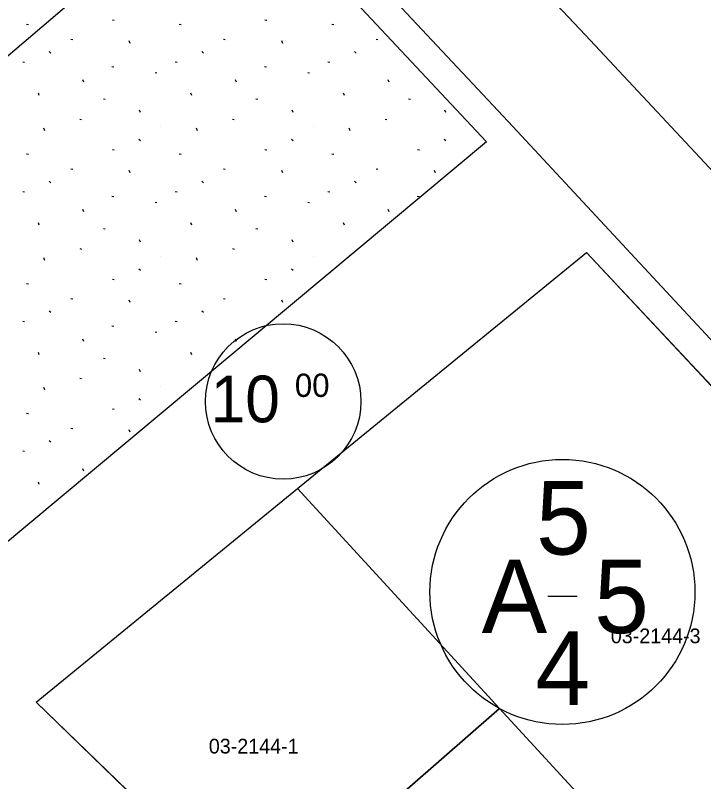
# Model space of a CAD drawing. Extents: x 413946 to 415528, y 4453939 to 4454944.
# Drawn here: x 413992.5 to 414039.2, y 4454203.5 to 4454255.6 of the extents above; entities that cross this region are included whole.
import ezdxf

# ---------------------------------------------------------------- set-up
doc = ezdxf.new("R2010")
doc.units = 0
for name, color, linetype in [('0_KADASTRO', 7, 'Continuous'), ('Level 28', 7, 'Continuous'), ('Level 41', 7, 'Continuous'), ('Level 54', 7, 'Continuous'), ('Level 62', 7, 'Continuous'), ('SEMBOL', 7, 'Continuous')]:
    doc.layers.add(name, color=color, linetype=linetype)

msp = doc.modelspace()

# ---------------------------------------------------------------- linework, layer by layer
at = {"layer": '0_KADASTRO'}
msp.add_lwpolyline([(413945.566, 4454269.246), (413976.93, 4454296.8), (414006.54, 4454265.23), (413971.15, 4454235.05), (413945.566, 4454264.88)], dxfattribs=at)
for points in [[(414011.66, 4454223.42), (414031.3, 4454239.46), (414063.26, 4454205.27), (414044.87, 4454187.28), (414025.39, 4454208.48)], [(413993.9, 4454208.91), (414011.66, 4454223.42), (414025.39, 4454208.48), (414009.07, 4454194.23)], [(414009.07, 4454194.23), (414025.39, 4454208.48), (414044.87, 4454187.28), (414030.63, 4454173.35)]]:
    msp.add_lwpolyline(points, close=True, dxfattribs=at)
at = {"layer": 'Level 28'}
for p, q in [((413962.499, 4454313.068), (414024.505, 4454246.98)), ((414024.505, 4454246.98), (413987.639, 4454216.206)), ((414011.66, 4454223.42), (414031.3, 4454239.46)), ((414031.3, 4454239.46), (414063.26, 4454205.27)), ((413993.9, 4454208.91), (414011.66, 4454223.42)), ((414009.07, 4454194.23), (413993.9, 4454208.91))]:
    msp.add_line(p, q, dxfattribs=at)
at = {"layer": 'Level 41'}
for p, q in [((413999.081, 4454255.258), (413999.208, 4454255.233)), ((413999.081, 4454255.258), (413999.208, 4454255.233)), ((414009.449, 4454255.258), (414009.576, 4454255.233)), ((414009.449, 4454255.258), (414009.576, 4454255.233)), ((413993.261, 4454254.964), (413993.388, 4454254.94)), ((413993.261, 4454254.964), (413993.388, 4454254.94)), ((414003.629, 4454254.964), (414003.756, 4454254.94)), ((414003.629, 4454254.964), (414003.756, 4454254.94)), ((414013.997, 4454254.964), (414014.124, 4454254.94)), ((414013.997, 4454254.964), (414014.124, 4454254.94)), ((413996.261, 4454253.939), (413996.386, 4454253.915)), ((413996.261, 4454253.939), (413996.386, 4454253.915)), ((414000.295, 4454253.66), (414000.23, 4454253.822)), ((414000.295, 4454253.66), (414000.23, 4454253.822)), ((414006.629, 4454253.939), (414006.754, 4454253.915)), ((414006.629, 4454253.939), (414006.754, 4454253.915)), ((414010.663, 4454253.66), (414010.598, 4454253.822)), ((414010.663, 4454253.66), (414010.598, 4454253.822)), ((414016.997, 4454253.939), (414017.122, 4454253.915)), ((414016.997, 4454253.939), (414017.122, 4454253.915)), ((413994.786, 4454253.102), (413994.913, 4454253.002)), ((413994.786, 4454253.102), (413994.913, 4454253.002)), ((414005.154, 4454253.102), (414005.281, 4454253.002)), ((414005.154, 4454253.102), (414005.281, 4454253.002)), ((414015.522, 4454253.102), (414015.649, 4454253.002)), ((414015.522, 4454253.102), (414015.649, 4454253.002)), ((413992.991, 4454252.396), (413993.118, 4454252.372)), ((413992.991, 4454252.396), (413993.118, 4454252.372)), ((413999.054, 4454252.092), (413999.181, 4454252.068)), ((413999.054, 4454252.092), (413999.181, 4454252.068)), ((414003.359, 4454252.396), (414003.486, 4454252.372)), ((414003.359, 4454252.396), (414003.486, 4454252.372)), ((414009.422, 4454252.092), (414009.549, 4454252.068)), ((414009.422, 4454252.092), (414009.549, 4454252.068)), ((414013.727, 4454252.396), (414013.854, 4454252.372)), ((414013.727, 4454252.396), (414013.854, 4454252.372)), ((414001.984, 4454251.682), (414002.11, 4454251.658)), ((414001.984, 4454251.682), (414002.11, 4454251.658)), ((414012.352, 4454251.682), (414012.478, 4454251.658)), ((414012.352, 4454251.682), (414012.478, 4454251.658)), ((413997.151, 4454251.023), (413997.085, 4454251.185)), ((413997.151, 4454251.023), (413997.085, 4454251.185)), ((414007.519, 4454251.023), (414007.453, 4454251.185)), ((414007.519, 4454251.023), (414007.453, 4454251.185)), ((414017.887, 4454251.023), (414017.821, 4454251.185)), ((414017.887, 4454251.023), (414017.821, 4454251.185)), ((413994.12, 4454250.108), (413994.055, 4454250.272)), ((413994.12, 4454250.108), (413994.055, 4454250.272)), ((413998.47, 4454249.888), (413998.596, 4454249.864)), ((413998.47, 4454249.888), (413998.596, 4454249.864)), ((414004.488, 4454250.108), (414004.423, 4454250.272)), ((414004.488, 4454250.108), (414004.423, 4454250.272)), ((414008.838, 4454249.888), (414008.964, 4454249.864)), ((414008.838, 4454249.888), (414008.964, 4454249.864)), ((414014.856, 4454250.108), (414014.791, 4454250.272)), ((414014.856, 4454250.108), (414014.791, 4454250.272)), ((414019.206, 4454249.888), (414019.332, 4454249.864)), ((414019.206, 4454249.888), (414019.332, 4454249.864)), ((414000.992, 4454248.959), (414000.928, 4454249.12)), ((414000.992, 4454248.959), (414000.928, 4454249.12)), ((414011.36, 4454248.959), (414011.296, 4454249.12)), ((414011.36, 4454248.959), (414011.296, 4454249.12)), ((414021.728, 4454248.959), (414021.664, 4454249.12)), ((414021.728, 4454248.959), (414021.664, 4454249.12)), ((413996.866, 4454248.52), (413996.993, 4454248.496)), ((413996.866, 4454248.52), (413996.993, 4454248.496)), ((414007.234, 4454248.52), (414007.361, 4454248.496)), ((414007.234, 4454248.52), (414007.361, 4454248.496)), ((414017.602, 4454248.52), (414017.729, 4454248.496)), ((414017.602, 4454248.52), (414017.729, 4454248.496)), ((413994.502, 4454247.726), (413994.437, 4454247.888)), ((413994.502, 4454247.726), (413994.437, 4454247.888)), ((414002.35, 4454247.995), (414002.359, 4454247.994)), ((414002.35, 4454247.995), (414002.359, 4454247.994)), ((414004.87, 4454247.726), (414004.805, 4454247.888)), ((414004.87, 4454247.726), (414004.805, 4454247.888)), ((414012.718, 4454247.995), (414012.727, 4454247.994)), ((414012.718, 4454247.995), (414012.727, 4454247.994)), ((414015.238, 4454247.726), (414015.173, 4454247.888)), ((414015.238, 4454247.726), (414015.173, 4454247.888)), ((414023.086, 4454247.995), (414023.095, 4454247.994)), ((414023.086, 4454247.995), (414023.095, 4454247.994)), ((414000.875, 4454247.156), (414001.002, 4454247.058)), ((414000.875, 4454247.156), (414001.002, 4454247.058)), ((414011.243, 4454247.156), (414011.37, 4454247.058)), ((414011.243, 4454247.156), (414011.37, 4454247.058)), ((414021.611, 4454247.156), (414021.738, 4454247.058)), ((414021.611, 4454247.156), (414021.738, 4454247.058)), ((413999.081, 4454246.452), (413999.208, 4454246.427)), ((413999.081, 4454246.452), (413999.208, 4454246.427)), ((414009.449, 4454246.452), (414009.576, 4454246.427)), ((414009.449, 4454246.452), (414009.576, 4454246.427)), ((414019.817, 4454246.452), (414019.944, 4454246.427)), ((414019.817, 4454246.452), (414019.944, 4454246.427)), ((413993.261, 4454246.158), (413993.388, 4454246.134)), ((413993.261, 4454246.158), (413993.388, 4454246.134)), ((414003.629, 4454246.158), (414003.756, 4454246.134)), ((414003.629, 4454246.158), (414003.756, 4454246.134)), ((414013.997, 4454246.158), (414014.124, 4454246.134)), ((414013.997, 4454246.158), (414014.124, 4454246.134)), ((413996.261, 4454245.133), (413996.386, 4454245.109)), ((413996.261, 4454245.133), (413996.386, 4454245.109)), ((414000.295, 4454244.854), (414000.23, 4454245.016)), ((414000.295, 4454244.854), (414000.23, 4454245.016)), ((414006.629, 4454245.133), (414006.754, 4454245.109)), ((414006.629, 4454245.133), (414006.754, 4454245.109)), ((414010.663, 4454244.854), (414010.598, 4454245.016)), ((414010.663, 4454244.854), (414010.598, 4454245.016)), ((414016.997, 4454245.133), (414017.122, 4454245.109)), ((414016.997, 4454245.133), (414017.122, 4454245.109)), ((414021.031, 4454244.854), (414020.966, 4454245.016)), ((414021.031, 4454244.854), (414020.966, 4454245.016)), ((413994.786, 4454244.296), (413994.913, 4454244.196)), ((413994.786, 4454244.296), (413994.913, 4454244.196)), ((414005.154, 4454244.296), (414005.281, 4454244.196)), ((414005.154, 4454244.296), (414005.281, 4454244.196)), ((414015.522, 4454244.296), (414015.649, 4454244.196)), ((414015.522, 4454244.296), (414015.649, 4454244.196)), ((413992.991, 4454243.59), (413993.118, 4454243.566)), ((413992.991, 4454243.59), (413993.118, 4454243.566)), ((414003.359, 4454243.59), (414003.486, 4454243.566)), ((414003.359, 4454243.59), (414003.486, 4454243.566)), ((414013.727, 4454243.59), (414013.854, 4454243.566)), ((414013.727, 4454243.59), (414013.854, 4454243.566)), ((413999.054, 4454243.286), (413999.181, 4454243.262)), ((413999.054, 4454243.286), (413999.181, 4454243.262)), ((414009.422, 4454243.286), (414009.549, 4454243.262)), ((414009.422, 4454243.286), (414009.549, 4454243.262)), ((414019.79, 4454243.286), (414019.917, 4454243.262)), ((414019.79, 4454243.286), (414019.917, 4454243.262)), ((414001.984, 4454242.876), (414002.11, 4454242.852)), ((414001.984, 4454242.876), (414002.11, 4454242.852)), ((414012.352, 4454242.876), (414012.478, 4454242.852)), ((414012.352, 4454242.876), (414012.478, 4454242.852)), ((413997.151, 4454242.217), (413997.085, 4454242.379)), ((413997.151, 4454242.217), (413997.085, 4454242.379)), ((414007.519, 4454242.217), (414007.453, 4454242.379)), ((414007.519, 4454242.217), (414007.453, 4454242.379)), ((414017.887, 4454242.217), (414017.821, 4454242.379)), ((414017.887, 4454242.217), (414017.821, 4454242.379)), ((413994.12, 4454241.302), (413994.055, 4454241.466)), ((413994.12, 4454241.302), (413994.055, 4454241.466)), ((413998.47, 4454241.082), (413998.596, 4454241.058)), ((413998.47, 4454241.082), (413998.596, 4454241.058)), ((414004.488, 4454241.302), (414004.423, 4454241.466)), ((414004.488, 4454241.302), (414004.423, 4454241.466)), ((414008.838, 4454241.082), (414008.964, 4454241.058)), ((414008.838, 4454241.082), (414008.964, 4454241.058)), ((414014.856, 4454241.302), (414014.791, 4454241.466)), ((414014.856, 4454241.302), (414014.791, 4454241.466)), ((414000.992, 4454240.153), (414000.928, 4454240.314)), ((414000.992, 4454240.153), (414000.928, 4454240.314)), ((414011.36, 4454240.153), (414011.296, 4454240.314)), ((414011.36, 4454240.153), (414011.296, 4454240.314)), ((413996.866, 4454239.714), (413996.993, 4454239.69)), ((413996.866, 4454239.714), (413996.993, 4454239.69)), ((414007.234, 4454239.714), (414007.361, 4454239.69)), ((414007.234, 4454239.714), (414007.361, 4454239.69)), ((413994.502, 4454238.92), (413994.437, 4454239.082)), ((413994.502, 4454238.92), (413994.437, 4454239.082)), ((414002.35, 4454239.189), (414002.359, 4454239.188)), ((414002.35, 4454239.189), (414002.359, 4454239.188)), ((414004.87, 4454238.92), (414004.805, 4454239.082)), ((414004.87, 4454238.92), (414004.805, 4454239.082)), ((414012.718, 4454239.189), (414012.727, 4454239.188)), ((414012.718, 4454239.189), (414012.727, 4454239.188)), ((414000.875, 4454238.35), (414001.002, 4454238.252)), ((414000.875, 4454238.35), (414001.002, 4454238.252)), ((414011.243, 4454238.35), (414011.37, 4454238.252)), ((414011.243, 4454238.35), (414011.37, 4454238.252)), ((413993.261, 4454237.352), (413993.388, 4454237.328)), ((413993.261, 4454237.352), (413993.388, 4454237.328)), ((413999.081, 4454237.646), (413999.208, 4454237.621)), ((413999.081, 4454237.646), (413999.208, 4454237.621)), ((414003.629, 4454237.352), (414003.756, 4454237.328)), ((414003.629, 4454237.352), (414003.756, 4454237.328)), ((414009.449, 4454237.646), (414009.576, 4454237.621)), ((414009.449, 4454237.646), (414009.576, 4454237.621)), ((413996.261, 4454236.327), (413996.386, 4454236.303)), ((413996.261, 4454236.327), (413996.386, 4454236.303)), ((414006.629, 4454236.327), (414006.754, 4454236.303)), ((414006.629, 4454236.327), (414006.754, 4454236.303)), ((414000.295, 4454236.048), (414000.23, 4454236.21)), ((414000.295, 4454236.048), (414000.23, 4454236.21)), ((414010.663, 4454236.048), (414010.598, 4454236.21)), ((414010.663, 4454236.048), (414010.598, 4454236.21)), ((413994.786, 4454235.49), (413994.913, 4454235.39)), ((413994.786, 4454235.49), (413994.913, 4454235.39)), ((414005.154, 4454235.49), (414005.281, 4454235.39)), ((414005.154, 4454235.49), (414005.281, 4454235.39)), ((413992.991, 4454234.784), (413993.118, 4454234.76)), ((413992.991, 4454234.784), (413993.118, 4454234.76)), ((414003.359, 4454234.784), (414003.486, 4454234.76)), ((414003.359, 4454234.784), (414003.486, 4454234.76)), ((413999.054, 4454234.48), (413999.181, 4454234.456)), ((413999.054, 4454234.48), (413999.181, 4454234.456)), ((414009.422, 4454234.48), (414009.511, 4454234.463)), ((414009.422, 4454234.48), (414009.511, 4454234.463)), ((414001.984, 4454234.07), (414002.11, 4454234.046)), ((414001.984, 4454234.07), (414002.11, 4454234.046)), ((413997.151, 4454233.411), (413997.085, 4454233.573)), ((413997.151, 4454233.411), (413997.085, 4454233.573)), ((414007.519, 4454233.411), (414007.453, 4454233.573)), ((414007.519, 4454233.411), (414007.453, 4454233.573)), ((413994.12, 4454232.496), (413994.055, 4454232.66)), ((413994.12, 4454232.496), (413994.055, 4454232.66)), ((414004.488, 4454232.496), (414004.423, 4454232.66)), ((414004.488, 4454232.496), (414004.423, 4454232.66)), ((413998.47, 4454232.276), (413998.596, 4454232.252)), ((413998.47, 4454232.276), (413998.596, 4454232.252)), ((414000.992, 4454231.347), (414000.928, 4454231.508)), ((414000.992, 4454231.347), (414000.928, 4454231.508)), ((413996.866, 4454230.908), (413996.993, 4454230.884)), ((413996.866, 4454230.908), (413996.993, 4454230.884)), ((413994.502, 4454230.114), (413994.437, 4454230.276)), ((413994.502, 4454230.114), (413994.437, 4454230.276)), ((414002.35, 4454230.383), (414002.359, 4454230.382)), ((414002.35, 4454230.383), (414002.359, 4454230.382)), ((414000.875, 4454229.544), (414001.002, 4454229.446)), ((414000.875, 4454229.544), (414001.002, 4454229.446)), ((413993.261, 4454228.546), (413993.388, 4454228.522)), ((413993.261, 4454228.546), (413993.388, 4454228.522)), ((413999.081, 4454228.84), (413999.208, 4454228.815)), ((413999.081, 4454228.84), (413999.208, 4454228.815)), ((413996.261, 4454227.521), (413996.386, 4454227.497)), ((413996.261, 4454227.521), (413996.386, 4454227.497)), ((414000.295, 4454227.242), (414000.23, 4454227.404)), ((414000.295, 4454227.242), (414000.23, 4454227.404)), ((413994.786, 4454226.684), (413994.913, 4454226.584)), ((413994.786, 4454226.684), (413994.913, 4454226.584)), ((413992.991, 4454225.978), (413993.118, 4454225.954)), ((413992.991, 4454225.978), (413993.118, 4454225.954)), ((413997.151, 4454224.605), (413997.085, 4454224.767)), ((413997.151, 4454224.605), (413997.085, 4454224.767)), ((413994.12, 4454223.69), (413994.055, 4454223.854)), ((413994.12, 4454223.69), (413994.055, 4454223.854))]:
    msp.add_line(p, q, dxfattribs=at)
at = {"layer": 'Level 54'}
msp.add_lwpolyline([(414031.3, 4454239.46), (414063.26, 4454205.27), (414044.87, 4454187.28), (414030.63, 4454173.35), (414009.07, 4454194.23), (413993.9, 4454208.91), (414011.66, 4454223.42)], close=True, dxfattribs=at)
at = {"layer": 'Level 62'}
for points in [[(414031.227, 4454254.226), (414014.434, 4454271.989), (413984.645, 4454303.748), (413971.528, 4454317.991)], [(413965.273, 4454313.034), (414025.964, 4454248.348)], [(414107.905, 4454172.158), (414031.227, 4454254.226)], [(414025.964, 4454248.348), (414064.721, 4454206.636)]]:
    msp.add_lwpolyline(points, dxfattribs=at)
at = {"layer": 'SEMBOL'}
msp.add_line((414028.655, 4454216.099), (414030.655, 4454216.099), dxfattribs=at)
for centre, radius in [((414010.686, 4454229.335), 5.28), ((414029.655, 4454216.395), 9)]:
    msp.add_circle(centre, radius, dxfattribs=at)

# ---------------------------------------------------------------- texts
at = {"layer": '0_KADASTRO'}
for s, p in [('03-2144-3', (414032.939, 4454212.914)), ('03-2144-1', (414005.634, 4454205.422))]:
    msp.add_text(s, height=1, dxfattribs=at).set_placement(p)
at = {"layer": 'SEMBOL'}
for s, height, p in [('10', 3.1681, (414005.753, 4454227.92)), ('00', 1.584, (414011.478, 4454229.642)), ('5', 5, (414027.862, 4454218.938)), ('A', 5, (414024.163, 4454213.599)), ('5', 5, (414031.809, 4454213.599)), ('4', 5, (414027.817, 4454208.722))]:
    msp.add_text(s, height=height, dxfattribs=at).set_placement(p)

doc.saveas('drawing.dxf')
